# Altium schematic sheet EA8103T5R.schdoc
size 127 x 101 mm
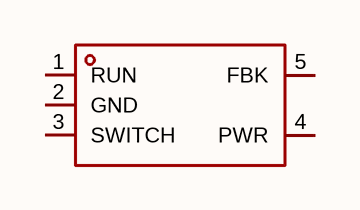
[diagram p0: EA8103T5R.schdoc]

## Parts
U?  ea8103t5r  [SOT-23-5_L2.9-W1.6-P0.95-LS2.8-BL]  (value not drawn)

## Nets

Not connected (* = marked no-connect by the designer): U? 1(RUN) 2(GND) 3(SWITCH) 4(PWR) 5(FBK)

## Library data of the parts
U? = ea8103t5r: 功能类型:降压型;工作电压:2.6V~6V;输出电压:1.13V;输出电流:1.2A;输出类型:可调;; Manufacturer: everanalog(申风); AddInBom: yes; ModelId: 018c57e721114987ae90467fe9f1d259; ModelTransform: 114.96,110.236,0,0,0,0,0,0,0; Function: 降压型; Output Voltage: 1.13V; Output Current: 1.2A; Frequency - Switching: 1.35MHz; Synchronous Rectifier: 是; Number of Outputs: 1; Topology: 降压式; Quiescent Current: 1uA; Switch tube (built-in/external): 内置; Output Type: 可调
